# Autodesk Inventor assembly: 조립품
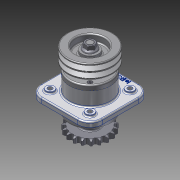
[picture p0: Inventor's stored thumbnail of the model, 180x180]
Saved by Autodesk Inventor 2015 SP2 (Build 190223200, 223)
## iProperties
Created: 2015-07
Part Number: 조립품
Document SubType Name: Assembly
Designer: AMC
Author: AMC
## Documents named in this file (12)
- C:\Users\AMC\Desktop\450735V1015\조립품.iam
- C:\Users\AMC\Desktop\450735V1015\본체.ipt
- C:\Users\AMC\Desktop\450735V1015\2-커버.ipt
- C:\Users\AMC\Desktop\450735V1015\3-축.ipt
- C:\Users\AMC\Desktop\450735V1015\4-V벨트풀리.ipt
- C:\Users\AMC\Desktop\450735V1015\5-체인 스프로킷.ipt
- C:\Users\AMC\Desktop\450735V1015\6-베어링 6206.ipt
- C:\Users\AMC\Desktop\450735V1015\7-부시.ipt
- C:\Users\AMC\Desktop\450735V1015\8-오일실 30x42.ipt
- C:\Users\AMC\Desktop\450735V1015\9-M16-너트.ipt
- C:\Users\AMC\Desktop\450735V1015\10-M6.ipt
- C:\Users\AMC\Desktop\450735V1015\11-키 6x6.ipt
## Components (22 placed, 10 different names)
1. 2-커버:1
2. 3-축:1 — 플러쉬:1
3. 4-V벨트풀리:1 — 각도:1
4. 5-체인 스프로킷:1 — 각도:2
5. 6-베어링 6206:1
6. 7-부시:1
7. 8-8-오일실 30x42:1
8. 9-M16 너트:1
9. 11-키 6x6:1 — 각도:1
10. 6-베어링 6206:2
11. 2-커버:2
12. 8-8-오일실 30x42:2
13. 11-키 6x6:2 — 각도:2
14. 9-M16 너트:2
15. 10-M6:1
16. 10-M6:3
17. 10-M6:4
18. 10-M6:5
19. 10-M6:2
20. 10-M6:6
21. 10-M6:7
22. 10-M6:8
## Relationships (3: Angle 2, Flush 1)
- 플러쉬:1 [Flush]: 3-축:1
- 각도:1 [Angle]: 4-V벨트풀리:1 ↔ 11-키 6x6:1
- 각도:2 [Angle]: 5-체인 스프로킷:1 ↔ 11-키 6x6:2
